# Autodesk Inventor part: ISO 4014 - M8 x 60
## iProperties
Comments: To add or edit properties for Autodesk Inventor files, use iProperties.
Created: 2004-08
Part Number: ISO 4014 - M8 x 60
Vendor: Autodesk Inc.
Document SubType Name: Modeling
Designer: John Blackburn
Material: Default
Description: Hex-Head Bolt
Standard: ISO 4014
Size Designation: M8 x 60
Alert: To add or edit properties for Autodesk Inventor files, use iProperties.
Control State: 0
Master: False
Checked Out: False
Shininess: 64.0
Length Units: 11269
Angle Units: 11279
Time Units: 11290
Mass Units: 11283
Length Display Precision: 3
Angle Display Precision: 2
Compacted: True
EGR: 1
Density: 0.0
Volumn: 0.0
Area: 0.0
PropertySet Name: Model Information
Author: John Blackburn
Revision Number: 8
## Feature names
1. Body [Revolution]
2. Head [Extrusion]
3. Chamfer1 [Revolution]
4. Chamfer2
